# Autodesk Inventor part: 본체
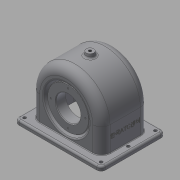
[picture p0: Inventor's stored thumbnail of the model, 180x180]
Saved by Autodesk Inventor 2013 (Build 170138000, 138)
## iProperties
Created: 2015-09
Part Number: 본체
Material: 일반
Document SubType Name: Modeling
Designer: Administrator
Density: 1 g/cm^3
Author: Administrator
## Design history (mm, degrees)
sketch "스케치1"
  geometry: L1 (-70, 52)-(70, 52); L2 (70, 52)-(70, -52); L3 (70, -52)-(-70, -52); L4 (-70, -52)-(-70, 52); L5 (-57, 38.5)-(57, 38.5); L6 (57, 38.5)-(57, -38.5); L7 (57, -38.5)-(-57, -38.5); L8 (-57, -38.5)-(-57, 38.5); 11 further points
  constraints: 16 end point, 6 midpoint, 4 parallel, 4 point on line, 3 horizontal alignment, 3 vertical alignment, 2 horizontal, 2 perpendicular
  dimensions: "d0" = 140 distance of L1.start L1.end; "d2" = 104 distance of L1.end L2.end; "d3" = 77 distance of L5.start L7.end; "d4" = 114 distance of L7.end L6.end
extrude "돌출2" join sketch "스케치1" distance "d8" = 47; taper "d9" = 0 deg
sketch "스케치2"
  geometry: L1 (-57, 0)-(57, 0) reference; L2 (-57, 0)-(-57, 47) reference; L3 (57, 47)-(-57, 47) reference; L4 (57, 0)-(57, 47) reference; L5 (-57, 47)-(57, 47); L6 (-51, 47)-(-51, 0); L7 (51, 47)-(51, 0); L8 (-51, 0)-(51, 0); A1 r 57 centre (0, 47) between (57, 47) and (-57, 47); A2 r 51 centre (0, 47) between (51, 47) and (-51, 47); 1 further point
  constraints: 8 end point, 5 point on line, 4 point on circle, 2 centre point, 2 collinear, 2 perpendicular, 2 tangent, 1 coincident, 1 midpoint
  dimensions: "d133" = 102 diameter of A2
  node "투영된 루프2"
extrude "돌출5" join sketch "스케치2" stored distance "d20" = 77; taper "d21" = 0 deg
extrude "돌출10" cut sketch "스케치2" stored distance "d136" = 67; taper "d137" = 0 deg
extrude "돌출4" join sketch "스케치1" distance "d16" = 7; taper "d17" = 0 deg
fillet "모깎기2" dims "d18" = 14
fillet "모깎기4" dims "d22" = 7
sketch "스케치4"
  geometry: L1 (63, -47)-(-63, -47) reference; C1 r 33 at (0, 0); A1 r 43 centre (0, 0) between (43, 0) and (-43, 0) reference; 1 further point
  constraints: 1 centre point, 1 coincident
  dimensions: "d25" = 66 diameter of C1
extrude "돌출6" cut sketch "스케치4" distance "d27" = 3; taper "d28" = 0 deg
sketch "스케치5"
  geometry: C1 r 33 at (0, 0) reference; C2 r 28 at (0, 0); 1 further point
  constraints: 1 centre point, 1 coincident
  dimensions: "d29" = 56 diameter of C2
extrude "돌출7" join sketch "스케치5" distance "d32" = 16; taper "d33" = 0 deg
hole "구멍1" diameter "d36" = 40; stored, may be unused: countersink angle "d40" = 90 deg, drill point angle "d42" = 0 deg; dims "d34" = 10, "d35" = 10, "d37" = 6, "d38" = 4, "d39" = 2, "d41" = 16
sketch "스케치6"
  geometry: C1 r 31 at (0, 0); A1 r 43 centre (0, 0) between (-43, 0) and (43, 0) reference; 1 further point
  constraints: 1 centre point, 1 coincident
  dimensions: "d43" = 62 diameter of C1
extrude "돌출8" join sketch "스케치6" distance "d45" = 10; taper "d46" = 0 deg
hole "구멍2" diameter "d49" = 40; stored, may be unused: countersink angle "d53" = 90 deg, drill point angle "d55" = 0 deg; dims "d47" = 10, "d48" = 10, "d50" = 6, "d51" = 4, "d52" = 2, "d54" = 16
sketch "스케치8"
  geometry: C1 r 20 at (0, 0) reference; 2 further points
  constraints: 1 vertical alignment
  dimensions: "d56" = 24 distance of point (0, -24) C1.centre
hole "구멍3" sketch "스케치8" at (0, -24) diameter "d57" = 2.459; stored, may be unused: countersink angle "d61" = 90 deg, drill point angle "d63" = 118 deg; dims "d58" = 6, "d59" = 4, "d60" = 2, "d62" = 8
node "작업 평면1"
sketch "스케치10"
  geometry: C1 r 6 at (0, 0); 1 further point
  constraints: 1 centre point, 1 coincident
  dimensions: "d79" = 12 diameter of C1
extrude "돌출9" join sketch "스케치10" stored distance "d81" = 10; taper "d82" = 10 deg
hole "구멍5" diameter "d85" = 4.459; stored, may be unused: countersink angle "d89" = 90 deg, drill point angle "d91" = 0 deg; dims "d83" = 10, "d84" = 10, "d86" = 15, "d87" = 4, "d88" = 2, "d90" = 15
sketch "스케치11"
  geometry: L1 (-33.5, 47)-(-24.5, 47) reference; L2 (-24.5, 47)-(-24.5, 47) reference; L3 (-33.5, 47)-(-24.5, 47) reference; L4 (-33.5, 47)-(-33.5, 47) reference; L5 (-38.5, 47)-(-24.5, 47) reference; L6 (-24.5, 47)-(-24.5, 47) reference; L7 (-38.5, 47)-(-24.5, 47) reference; L8 (-38.5, 47)-(-38.5, 47) reference; L9 (-19.5, 19)-(-19.5, 75) reference; L10 (-19.5, 75)-(-33.5, 86.747); L11 (-38.5, 84.416)-(-34.29, 80.883); L12 (-38.5, 47)-(-38.5, 90) reference; L13 (-35.5, 14)-(-35.5, 80) reference; L14 (-35.5, 80)-(-34.611, 80); L15 (-38.5, 80)-(-35.5, 80) reference; L16 (-38.5, 84.416)-(-38.5, 80); L17 (-35.5, 80)-(-38.5, 80); L18 (-33.5, 86.747)-(-33.5, 74.973); L19 (-33.5, 74.973)-(-19.5, 75); L20 (-38.5, 47)-(-19.5, 47); L21 (-33.5, 98)-(-33.5, 47) reference; A1 r 0.5 centre (-34.611, 80.5) between (-34.611, 80) and (-34.29, 80.883); 6 further points
  constraints: 16 end point, 2 collinear, 2 perpendicular, 2 point on circle, 2 tangent, 1 centre point, 1 midpoint, 1 point on line
  dimensions: "d92" = 50 deg angle of L9 L10; "d93" = 5 distance between parallel lines of L11 L10; "d95" = 0.5 radius of A1
  node "투영된 루프4"
  node "투영된 루프5"
revolve "회전1" stored, may be unused: angle "d96" = 90 deg
revolve "회전2" stored, may be unused: angle "d97" = 90 deg
sketch "스케치12"
  geometry: C1 r 20 at (0, 0) reference; 2 further points
  constraints: 1 vertical alignment
  dimensions: "d98" = 28 distance of C1.centre point (0, 28)
hole "구멍6" sketch "스케치12" at (0, 28) diameter "d99" = 2.459; stored, may be unused: countersink angle "d103" = 90 deg, drill point angle "d105" = 118 deg; dims "d100" = 7, "d101" = 4, "d102" = 2, "d104" = 9
chamfer "모따기1" distance "d106" = 1; stored, may be unused: second distance "d107" = 2, angle "d108" = 45 deg
sketch "스케치13"
  geometry: L1 (-70, 45)-(-70, -45) reference; L2 (-63, -52)-(63, -52) reference; 2 further points
  dimensions: "d109" = 8 distance from line of point (-62, -44) L2; "d110" = 8 distance from line of point (-62, -44) L1
hole "구멍7" sketch "스케치13" at (-62, -44) diameter "d111" = 5; stored, may be unused: countersink angle "d115" = 90 deg, drill point angle "d117" = 118 deg; dims "d112" = 7, "d113" = 4, "d114" = 2, "d116" = 9
sketch "스케치14"
  geometry: L1 (0, -14)-(40, -14) reference; L2 (47, 69.5)-(47, -20.5) reference; 2 further points
  constraints: 1 other
  dimensions: "d124" = 38.5 distance from line of point (17, 24.5) L1; "d125" = 30 distance from line of L2 point (17, 24.5)
feature "엠보싱1" sketch "스케치14" dims "d0" = 140, "d2" = 104, "d126" = 0.5, "d127" = 0
fillet "모깎기7" dims "d138" = 9
fillet "모깎기8" dims "d139" = 3
fillet "모깎기9" dims "d140" = 1
node "솔리드1"
pattern_circular "원형 패턴1" dims angle "d65" = 360 deg
pattern_linear "직사각형 패턴1" dims "d120" = 44, "d123" = 124
pattern_circular "원형 패턴3" dims angle "d131" = 360 deg
